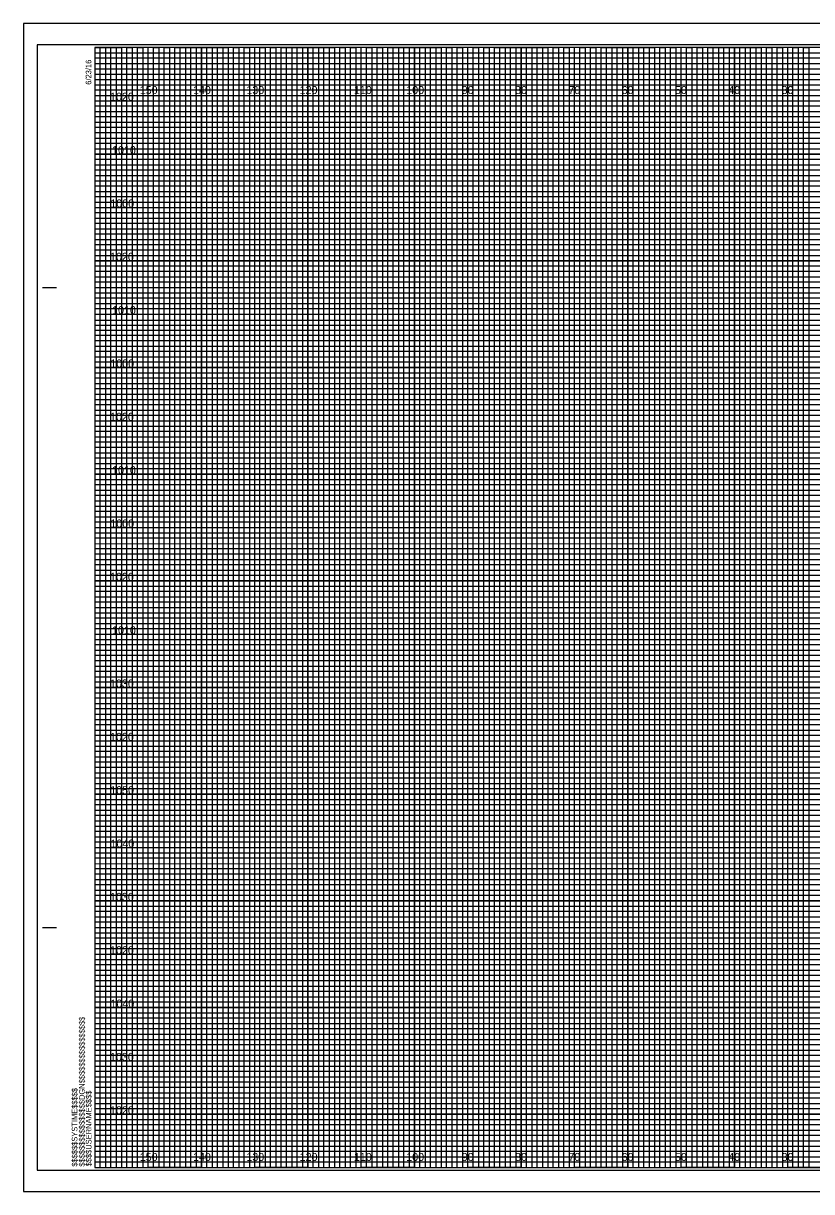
# Model space of a CAD drawing. Extents: x -13 to 323, y -5 to 215.
# Drawn here: x -13.4 to 134.5, y -4.5 to 214.5 of the extents above; entities that cross this region are included whole.
import ezdxf

# ---------------------------------------------------------------- set-up
doc = ezdxf.new("R2010")
doc.units = 0
for name, color, linetype in [('Exist Cross Section Cell', 7, 'Continuous'), ('Prop CMT Pvmt Course 1', 7, 'Continuous'), ('Prop CMT Pvmt Course 3', 7, 'Continuous'), ('Prop CMT Pvmt Surface', 7, 'Continuous'), ('Prop CMT Pvmt Surface Shoulder', 7, 'Continuous'), ('Prop CMT Shld Paved Course 1', 7, 'Continuous'), ('Prop CMT Shld Paved Course 2', 7, 'Continuous'), ('Prop CMT Shld Paved Course 3', 7, 'Continuous'), ('Prop CMT Slope Grass', 7, 'Continuous'), ('Prop CMT Subgrade Earthwork', 7, 'Continuous'), ('Scratch_Level_0', 7, 'Continuous')]:
    doc.layers.add(name, color=color, linetype=linetype)

msp = doc.modelspace()

# ---------------------------------------------------------------- linework, layer by layer
at = {"layer": 'Prop CMT Pvmt Course 3'}
msp.add_lwpolyline([(-13.4, -4.5), (323.3, -4.5), (323.3, 214.5), (-13.4, 214.5)], close=True, dxfattribs=at)
at = {"layer": 'Prop CMT Pvmt Surface'}
for p, q in [((10, 0), (10, 210)), ((20, 0), (20, 210)), ((30, 0), (30, 210)), ((40, 0), (40, 210)), ((50, 0), (50, 210)), ((60, 0), (60, 210)), ((70, 0), (70, 210)), ((80, 0), (80, 210)), ((90, 0), (90, 210)), ((100, 0), (100, 210)), ((110, 0), (110, 210)), ((120, 0), (120, 210)), ((130, 0), (130, 210)), ((0, 200), (320, 200)), ((0, 190), (320, 190)), ((0, 180), (320, 180)), ((0, 170), (320, 170)), ((0, 160), (320, 160)), ((0, 150), (320, 150)), ((0, 140), (320, 140)), ((0, 130), (320, 130)), ((0, 120), (320, 120)), ((0, 110), (320, 110)), ((0, 100), (320, 100)), ((0, 90), (320, 90)), ((0, 80), (320, 80)), ((0, 70), (320, 70)), ((0, 60), (320, 60)), ((0, 50), (320, 50)), ((0, 40), (320, 40)), ((0, 30), (320, 30)), ((0, 20), (320, 20)), ((0, 10), (320, 10))]:
    msp.add_line(p, q, dxfattribs=at)
at = {"layer": 'Prop CMT Pvmt Surface Shoulder'}
for p, q in [((323.3, 214.5), (-13.4, 214.5)), ((-13.4, 214.5), (-13.4, -4.5)), ((-13.4, -4.5), (323.3, -4.5))]:
    msp.add_line(p, q, dxfattribs=at)
at = {"layer": 'Prop CMT Shld Paved Course 1'}
for p, q in [((0, 209), (260, 209)), ((260, 207.98), (0, 207.98)), ((0, 207.98), (0, 207)), ((0, 207), (260, 207)), ((260, 205.89), (0, 205.89)), ((0, 205.89), (0, 204)), ((0, 204), (320, 204))]:
    msp.add_line(p, q, dxfattribs=at)
for points in [[(0, 203), (270, 203), (320, 203), (320, 202), (0, 202)], [(0, 201), (320, 201), (320, 199), (0, 199)], [(0, 198), (320, 198), (320, 197), (0, 196.98)], [(0, 196), (320, 196), (320, 194), (0, 194)], [(0, 193), (320, 193), (320, 192), (0, 192)], [(0, 191), (320, 191), (320, 189), (0, 189)], [(0, 188), (320, 188), (320, 187), (0, 187)], [(0, 186), (320, 186), (320, 184), (0, 184)], [(0, 183), (320, 183), (320, 182), (0, 182)], [(0, 181), (320, 181), (320, 179), (0, 179)], [(0, 178), (320, 178), (320, 177), (0, 177)], [(0, 176), (320, 176), (320, 173.95), (320, 173), (320, 172), (0, 172)], [(0, 174), (320, 174), (320, 173), (0, 173)], [(0, 171), (320, 171), (320, 169), (0, 169.03)], [(0, 169.03), (320, 169), (320, 168), (0, 168)], [(0, 167), (320, 167), (320, 166), (0, 166)], [(0, 164), (320, 164), (320, 163), (0, 163)], [(0, 162), (320, 162), (320, 161), (0, 161)], [(-0.07, 158.89), (320, 158.89), (320, 157.88), (-0.07, 157.88)], [(0, 157), (320, 157), (320, 156), (0, 156)], [(0, 154), (320, 154), (320, 153), (0, 153)], [(0, 152), (320, 152), (320, 151), (0, 151)], [(0, 149), (320, 149), (320, 148), (0, 148)], [(0, 147), (320, 147), (320, 146), (0, 146)], [(0, 144), (320, 144), (320, 143), (0, 143)], [(0, 142), (320, 142), (320, 141), (0, 141)], [(0, 139), (320, 139), (319.99, 137.98), (0, 138)], [(0, 137), (320, 137), (320, 136), (0, 136)], [(0, 134), (320, 134), (320, 133), (0, 133)], [(0, 132), (320, 132), (320, 131), (0, 131)], [(0, 129), (320, 129), (320, 128), (0, 128)], [(0, 127), (320, 127), (320, 126), (0, 126)], [(0, 124), (320, 124), (320, 123), (0, 123)], [(0, 122), (320, 122), (320, 121), (0, 121)], [(0, 119), (320, 119), (320, 118), (0, 118)], [(0, 116.99), (320.07, 116.91), (320, 116), (0, 116)], [(0, 114), (320, 114), (320, 113), (0, 113)], [(0, 112), (320, 112), (320, 111), (0, 111)], [(0, 109), (320, 109), (320, 108), (0, 108)], [(0, 107), (320, 107), (320, 106), (0, 106)], [(0, 104), (320, 104), (320, 103), (0, 103)], [(0, 102), (320, 102), (320, 101), (0, 101)], [(0, 99), (320, 99), (320, 98), (0, 98)], [(0, 97), (320, 97), (320, 96), (0, 96)], [(0, 94), (320, 94), (320, 93), (0, 93)], [(0, 92), (320, 92), (320, 91), (0, 91)], [(0, 89), (320, 89), (320, 88), (0, 88)], [(0, 87), (320, 87), (320, 86), (0, 86)], [(0, 84), (320, 84), (320, 83), (0, 83)], [(0, 82), (320, 82), (320, 81), (0, 81)], [(0, 79), (320, 79), (319.99, 77.98), (0, 78)], [(0, 77), (320, 77), (320, 76), (0, 76)], [(0, 74), (320, 74), (320, 73), (0, 73)], [(0, 72), (320, 72), (320, 71), (0, 71)], [(0, 69), (320, 69), (320, 68), (0, 68)], [(0, 67), (320, 67), (320, 66), (0, 66)], [(0, 64), (320, 64), (320, 63), (0, 63)], [(0, 62), (320, 62), (320, 61), (0, 61)], [(0, 59), (320, 59), (320, 58), (0, 58)], [(0, 56.99), (320.07, 56.91), (320, 56), (0, 56)], [(0, 54), (320, 54), (320, 53), (0, 53)], [(0, 52), (320, 52), (320, 51), (0, 51)], [(0, 49), (320, 49), (320, 48), (0, 48)], [(0, 47), (320, 47), (320, 46), (0, 46)], [(0, 44), (320, 44), (320, 43), (0, 43)], [(0, 42), (320, 42), (320, 41), (0, 41)], [(0, 39), (320, 39), (320, 38), (0, 38)], [(0, 37), (320, 37), (320, 36), (0, 36)], [(0, 34), (320, 34), (320, 33), (0, 33)], [(0, 32), (320, 32), (320, 31), (0, 31)], [(0, 29), (320, 29), (320, 28), (0, 28)], [(0, 27), (320, 27), (320, 26), (0, 26)], [(0, 24), (320, 24), (320, 23), (0, 23)], [(0, 22), (320, 22), (320, 21), (0, 21)], [(0, 19), (320, 19), (320, 18), (0, 18)], [(0, 17), (320, 17), (320, 16), (0, 16)], [(0, 14), (320, 14), (320, 13), (0, 13)], [(0, 12), (320, 12), (320, 11), (0, 11)], [(0, 9), (320, 9), (320, 8), (0, 8)], [(0, 7), (320, 7), (320, 6), (0, 6)], [(0, 4), (320, 4), (320, 3), (0, 3)], [(0, 2), (320, 2), (320, 1), (0, 1)]]:
    msp.add_lwpolyline(points, dxfattribs=at)
at = {"layer": 'Prop CMT Shld Paved Course 2'}
for p, q in [((-9.8, 165), (-7.3, 165)), ((-9.7, 165), (-7.2, 165)), ((-9.8, 45), (-7.3, 45)), ((-9.7, 45), (-7.2, 45)), ((0, 0), (0, 0)), ((0, 0), (0, 0)), ((0, 0), (0, 0)), ((0, 0), (0, 0)), ((0, 0), (0, 0)), ((0, 0), (0, 0)), ((0, 0), (0, 0))]:
    msp.add_line(p, q, dxfattribs=at)
msp.add_lwpolyline([(320, 210), (0, 210), (0, 0), (320, 0)], close=True, dxfattribs=at)
at = {"layer": 'Prop CMT Shld Paved Course 3'}
for points in [[(0, 0), (1, 0), (1, 210), (2, 210), (2, 0)], [(2, 0), (3, 0), (3, 210), (4, 210), (4, 0)], [(5, 0), (6, 0), (6, 210), (7, 210), (7, 0)], [(7, 0), (8, 0), (8, 210), (9, 210), (9, 0)], [(10, 0), (11, 0), (11, 210), (12, 210), (12, 0)], [(12, 0), (13, 0), (13, 210), (14, 210), (14, 0)], [(15, 0), (16, 0), (16, 210), (17, 210), (17, 0)], [(17, 0), (18, 0), (18, 210), (19, 210), (19, 0)], [(20, 0), (21, 0), (21, 210), (22, 210), (22, 0)], [(22, 0), (23, 0), (23, 210), (24, 210), (24, 0)], [(25, 0), (26, 0), (26, 210), (27, 210), (27, 0)], [(27, 0), (28, 0), (28, 210), (29, 210), (29, 0)], [(30, 0), (31, 0), (31, 210), (32, 210), (32, 0)], [(32, 0), (33, 0), (33, 210), (34, 210), (34, 0)], [(35, 0), (36, 0), (36, 210), (37, 210), (37, 0)], [(37, 0), (38, 0), (38, 210), (39, 210), (39, 0)], [(40, 0), (41, 0), (41, 210), (42, 210), (42, 0)], [(42, 0), (43, 0), (43, 210), (44, 210), (44, 0)], [(45, 0), (46, 0), (46, 210), (47, 210), (47, 0)], [(47, 0), (48, 0), (48, 210), (49, 210), (49, 0)], [(50, 0), (51, 0), (51, 210), (52, 210), (52, 0)], [(52, 0), (53, 0), (53, 210), (54, 210), (54, 0)], [(55, 0), (56, 0), (56, 210), (57, 210), (57, 0)], [(57, 0), (58, 0), (58, 210), (59, 210), (59, 0)], [(60, 0), (61, 0), (61, 210), (62, 210), (62, 0)], [(62, 0), (63, 0), (63, 210), (64, 210), (64, 0)], [(65, 0), (66, 0), (66, 210), (67, 210), (67, 0)], [(67, 0), (68, 0), (68, 210), (69, 210), (69, 0)], [(70, 0), (71, 0), (71, 210), (72, 210), (72, 0)], [(72, 0), (73, 0), (73, 210), (74, 210), (74, 0)], [(75, 0), (76, 0), (76, 210), (77, 210), (77, 0)], [(77, 0), (78, 0), (78, 210), (79, 210), (79, 0)], [(80, 0), (81, 0), (81, 210), (82, 210), (82, 0)], [(82, 0), (83, 0), (83, 210), (84, 210), (84, 0)], [(85, 0), (86, 0), (86, 210), (87, 210), (87, 0)], [(87, 0), (88, 0), (88, 210), (89, 210), (89, 0)], [(90, 0), (91, 0), (91, 210), (92, 210), (92, 0)], [(92, 0), (93, 0), (93, 210), (94, 210), (94, 0)], [(95, 0), (96, 0), (96, 210), (97, 210), (97, 0)], [(97, 0), (98, 0), (98, 210), (99, 210), (99, 0)], [(100, 0), (101, 0), (101, 210), (102, 210), (102, 0)], [(102, 0), (103, 0), (103, 210), (104, 210), (104, 0)], [(105, 0), (106, 0), (106, 210), (107, 210), (107, 0)], [(107, 0), (108, 0), (108, 210), (109, 210), (109, 0)], [(110, 0), (111, 0), (111, 210), (112, 210), (112, 0)], [(112, 0), (113, 0), (113, 210), (114, 210), (114, 0)], [(115, 0), (116, 0), (116, 210), (117, 210), (117, 0)], [(117, 0), (118, 0), (118, 210), (119, 210), (119, 0)], [(120, 0), (121, 0), (121, 210), (122, 210), (122, 0)], [(122, 0), (123, 0), (123, 210), (124, 210), (124, 0)], [(125, 0), (126, 0), (126, 210), (127, 210), (127, 0)], [(127, 0), (128, 0), (128, 210), (129, 210), (129, 0)], [(130, 0), (131, 0), (131, 210), (132, 210), (132, 0)], [(132, 0), (133, 0), (133, 210), (134, 210), (134, 0)]]:
    msp.add_lwpolyline(points, dxfattribs=at)
at = {"layer": 'Prop CMT Slope Grass'}
for points in [[(0, 210), (5, 210), (5, 0), (15, 0), (15, 210), (25, 210), (25, 0), (35, 0), (35, 210), (45, 210), (45, 0), (55, 0), (55, 210), (65, 210), (65, 0), (75, 0), (75, 210), (85, 210), (85, 0), (95, 0), (95, 210), (105, 210), (105, 0), (115, 0), (115, 210), (125, 210), (125, 0), (135, 0)], [(0, 205), (275, 205)], [(0, 185), (320, 185), (320, 195), (0, 195)], [(0, 165), (320, 165), (320, 175), (0, 175)], [(0, 145), (320, 145), (320, 155), (0, 155)], [(0, 125), (320, 125), (320, 135), (0, 135)], [(0, 105), (320, 105), (320, 115), (0, 115)], [(0, 85), (320, 85), (320, 95), (0, 95)], [(0, 65), (320, 65), (320, 75), (0, 75)], [(0, 45), (320, 45), (320, 55), (0, 55)], [(0, 25), (320, 25), (320, 35), (0, 35)], [(0, 5), (320, 5), (320, 15), (0, 15)]]:
    msp.add_lwpolyline(points, dxfattribs=at)
at = {"layer": 'Prop CMT Subgrade Earthwork'}
msp.add_lwpolyline([(-10.8, -0.5), (322.4, -0.5), (322.4, 210.5), (-10.8, 210.5)], close=True, dxfattribs=at)
at = {"layer": 'Scratch_Level_0'}
for p, q in [((10, 210), (0, 210)), ((10, 0), (10, 210)), ((30, 210), (20, 210)), ((20, 210), (20, 0)), ((30, 0), (30, 210)), ((50, 210), (40, 210)), ((40, 210), (40, 0)), ((50, 0), (50, 210)), ((70, 210), (60, 210)), ((60, 210), (60, 0)), ((70, 0), (70, 210)), ((90, 210), (80, 210)), ((80, 210), (80, 0)), ((90, 0), (90, 210)), ((110, 210), (100, 210)), ((100, 210), (100, 0)), ((110, 0), (110, 210)), ((130, 210), (120, 210)), ((120, 210), (120, 0)), ((130, 0), (130, 210)), ((20, 0), (10, 0)), ((40, 0), (30, 0)), ((60, 0), (50, 0)), ((80, 0), (70, 0)), ((100, 0), (90, 0)), ((120, 0), (110, 0)), ((140, 0), (130, 0))]:
    msp.add_line(p, q, dxfattribs=at)
for points in [[(0, 200), (320, 200), (320, 190), (0, 190)], [(0, 180), (320, 180), (320, 170), (0, 170)], [(0, 160), (320, 160), (320, 150), (0, 150)], [(0, 140), (320, 140), (320, 130), (0, 130)], [(0, 120), (320, 120), (320, 110), (0, 110)], [(0, 100), (320, 100), (320, 90), (0, 90)], [(0, 80), (320, 80), (320, 70), (0, 70)], [(0, 60), (320, 60), (320, 50), (0, 50)], [(0, 40), (320, 40), (320, 30), (0, 30)], [(0, 20), (320, 20), (320, 10), (0, 10)]]:
    msp.add_lwpolyline(points, dxfattribs=at)

# ---------------------------------------------------------------- texts
at = {"layer": 'Exist Cross Section Cell'}
for s, p in [('150', (8.44, 201.25)), ('140', (18.44, 201.25)), ('130', (28.44, 201.25)), ('120', (38.44, 201.25)), ('110', (48.62, 201.25)), ('100', (58.44, 201.25)), ('90', (68.86, 201.25)), ('80', (78.86, 201.25)), ('70', (88.86, 201.25)), ('60', (98.86, 201.25)), ('50', (108.86, 201.25)), ('40', (118.86, 201.25)), ('30', (128.86, 201.25)), ('150', (8.44, 1.25)), ('140', (18.44, 1.25)), ('130', (28.44, 1.25)), ('120', (38.44, 1.25)), ('110', (48.62, 1.25)), ('100', (58.44, 1.25)), ('90', (68.86, 1.25)), ('80', (78.86, 1.25)), ('70', (88.86, 1.25)), ('60', (98.86, 1.25)), ('50', (108.86, 1.25)), ('40', (118.86, 1.25)), ('30', (128.86, 1.25))]:
    msp.add_text(s, height=1.5, dxfattribs=at).set_placement(p)
at = {"layer": 'Prop CMT Pvmt Course 1'}
for s, p in [('1020', (2.87, 200)), ('1010', (3.25, 190)), ('1000', (2.92, 180)), ('1020', (2.87, 170)), ('1010', (3.25, 160)), ('1000', (2.92, 150)), ('1020', (2.87, 140)), ('1010', (3.25, 130)), ('1000', (2.92, 120)), ('1020', (2.87, 110)), ('1010', (3.25, 100)), ('1030', (2.86, 90)), ('1020', (2.87, 80)), ('1050', (2.9, 70)), ('1040', (2.95, 60)), ('1030', (2.86, 50)), ('1020', (2.87, 40)), ('1040', (2.95, 30)), ('1030', (2.86, 20)), ('1020', (2.87, 10))]:
    msp.add_text(s, height=1.5, dxfattribs=at).set_placement(p)
at = {"layer": 'Prop CMT Shld Paved Course 2'}
for s, p in [('6/23/16', (-0.65, 203)), ('$$$$$$$$$$$$$$$$DGN$$$$$$$$$$$$$$$$', (-1.88, 0.18)), ('$$$$$$SYSTIME$$$$$', (-3.26, 0.18)), ('$$$$USERNAME$$$$', (-0.62, 0.23))]:
    msp.add_text(s, height=1.05, rotation=90, dxfattribs=at).set_placement(p)

doc.saveas('drawing.dxf')
